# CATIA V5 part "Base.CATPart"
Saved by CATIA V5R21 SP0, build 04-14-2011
Part number: Part1
Bounding box of the stored display mesh (mm): x -50 to 50, y -25 to 25, z 0 to 50
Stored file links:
  D:\CATIA V5R21 E-RESOURCES\CATIA-V5R21\catia-v5r21-Prts\c12_catia_v5r21_prt\c12_catia_v5r21figr_12-22\Base.CATPart
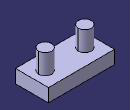
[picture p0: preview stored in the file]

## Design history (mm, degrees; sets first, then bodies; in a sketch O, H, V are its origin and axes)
Body1 (main body)
  Sketch1 on xy-plane, origin (0, 0, 0), H (1, 0, 0), V (0, 1, 0)
    line L1 (50, 25) -> (50, -25)
    line L2 (50, -25) -> (-50, -25)
    line L3 (-50, -25) -> (-50, 25)
    line L4 (-50, 25) -> (50, 25)
    circle A1 centre (-30, 0) radius 10
    point P5 (-30, 0)
    circle A2 centre (30, 0) radius 10
    length L2 = 100
    length L1 = 50
    radius A1 = 10
    distance P5 V = 30
    vertical: L1 V, L3 V
    horizontal: L2 H, L4 H
    equidistance: L1 L3 O, L2 L4 O
    coincidence: P5 H
    symmetry: A1 A2 V
  MultiPad1: profile Sketch1, domains (length 20; length 50; length 50)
